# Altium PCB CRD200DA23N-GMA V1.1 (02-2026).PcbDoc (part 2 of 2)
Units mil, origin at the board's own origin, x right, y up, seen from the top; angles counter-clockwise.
Board outline 11500 x 10500 mil, 6 copper layers (Top Layer, Layer 1, Layer 2, Layer 3, Layer 4, Bottom Layer), stack 92.199 mil thick; 97 components, 36 nets, 406 pads, 60 vias.
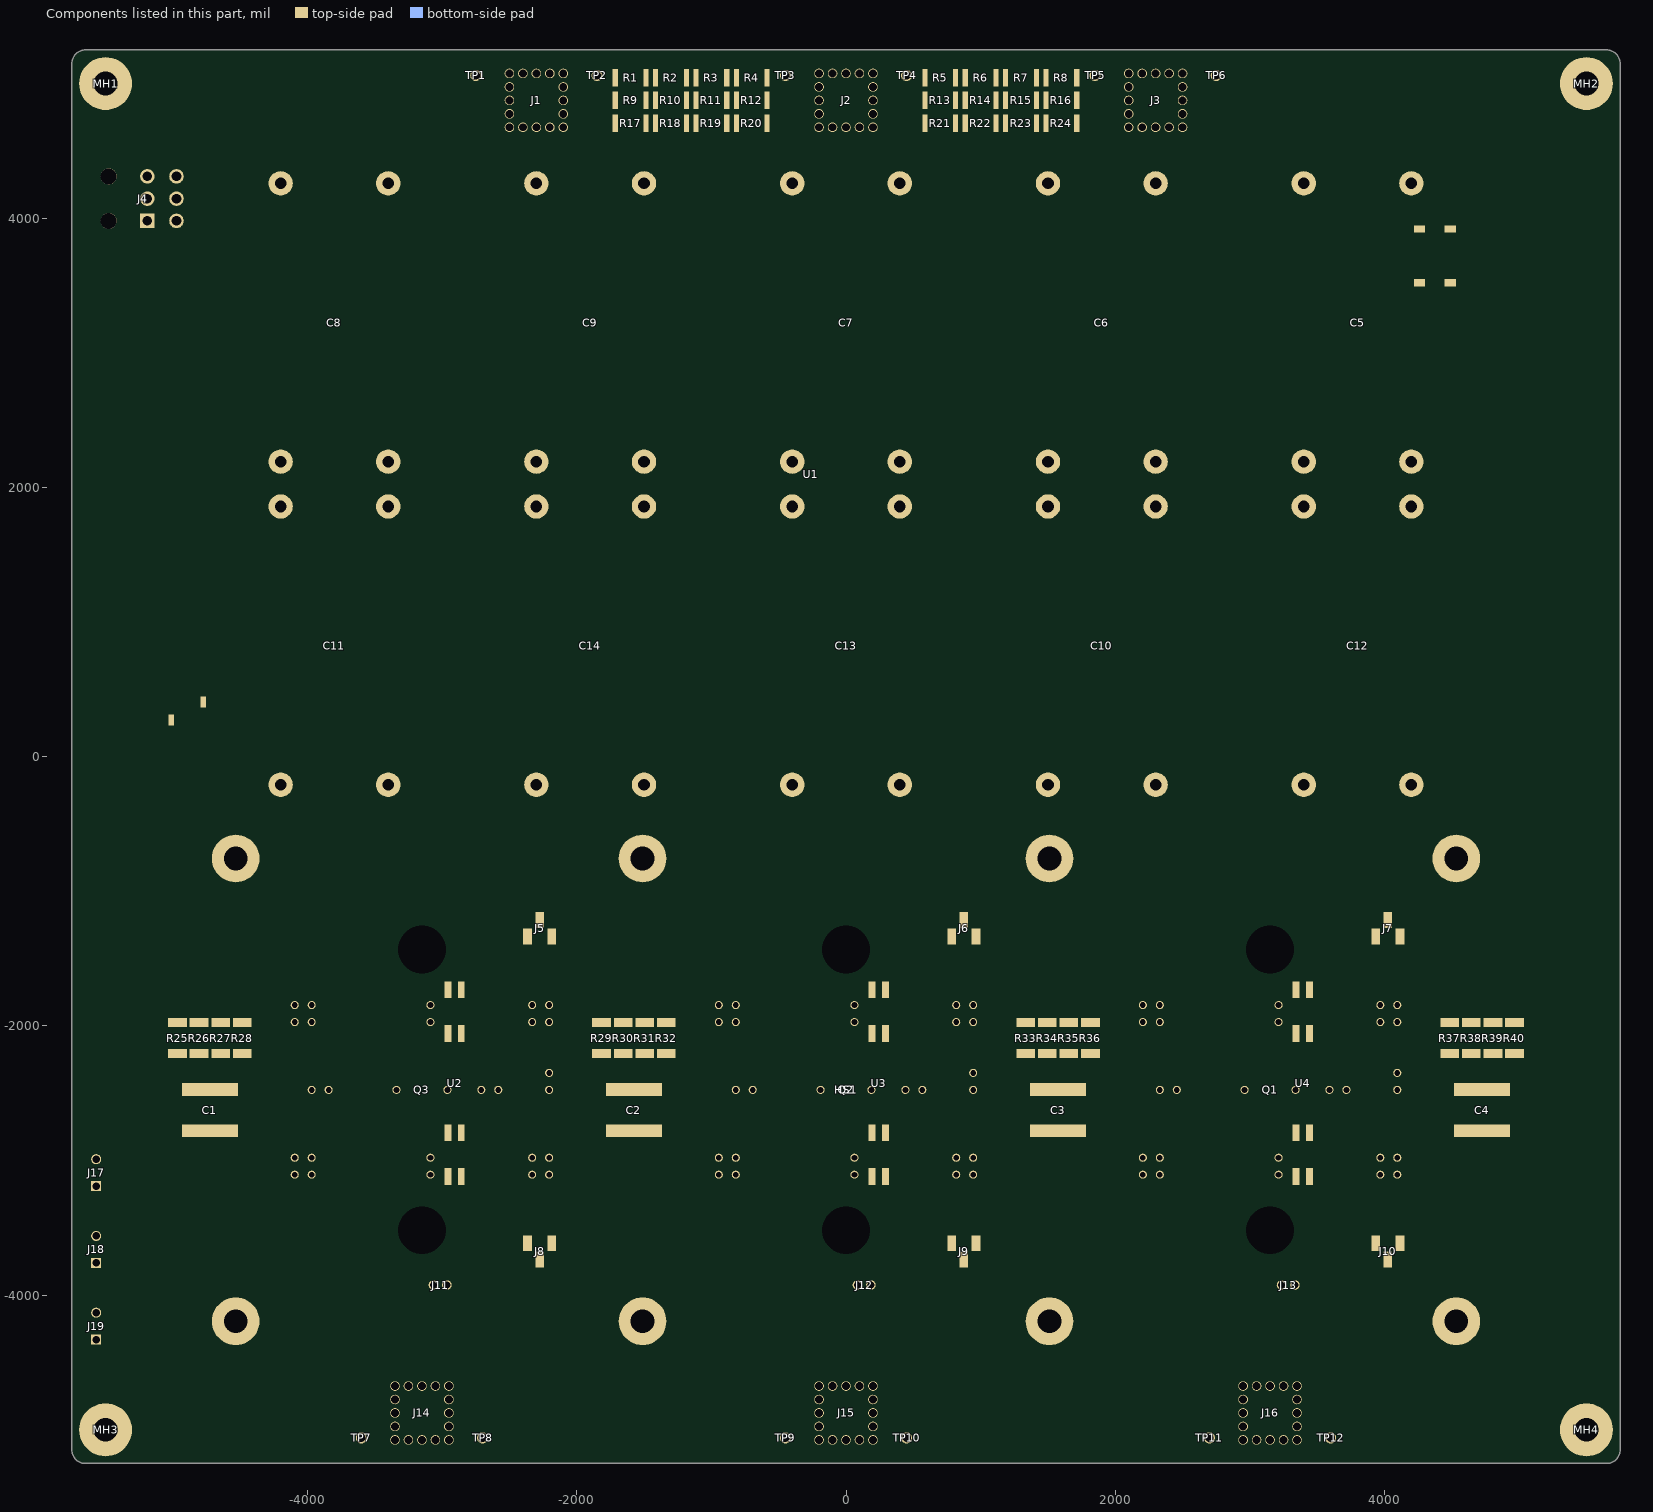
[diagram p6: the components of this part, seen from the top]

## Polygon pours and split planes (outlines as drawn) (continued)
+12V on Layer 2 "Layer 2-+12V" (solid, pour order 417): -5549.4,-4484.91 ccw(c-5555.06,-4380) -5450,-4380 -5450,95 cw(c-5344.94,95) -5348.49,200 -4841.51,200 ccw(c-4845.06,305) -4740,305 -4740,378.49 ccw(c-4845,374.94) -4845,480 -5345,480 cw(c-5345,585.06) -5450,581.51 -5450,3544.99 -5450,3545 cw(c-5345,3545) -5345,3650 -4905,3650 ccw(c-4905,3755) -4800,3755 -4800,4345.16 ccw(c-4904.83,4345.17) -4905,4450 -5545,4450 ccw(c-5545.11,4345.11) -5650,4345 -5650,-4383.5 ccw(c-5545,-4379.94)
U on Layer 1 "Layer 1-U" (solid, pour order 563): -4200.03,-5044.92 ccw(c-4094.97,-5044.91) -4094.97,-5149.97 -2201.54,-5149.97 ccw(c-2205.09,-5044.97) -2100.03,-5044.97 -2100.03,-3055 ccw(c-2203.28,-3053.25) -2205.03,-2950 -2410,-2950 ccw(c-2408.2,-3056.8) -2515,-3055 -2515,-3530 cw(c-2839.99,-3530.01) -2599.19,-3748.26 -2705,-3935 -2705,-3936.87 cw(c-2970.85,-3919.15) -2988.57,-4185 -3075,-4185 cw(c-3075,-3935) -3325,-3935 -3396.16,-3750.32 cw(c-3155,-3525) -3485,-3530 -3485,-3055 ccw(c-3591.8,-3056.8) -3590,-2950 -4094.97,-2950 ccw(c-4093.71,-3056.26) -4199.97,-3055 -4199.97,-5041.36 ccw(c-4094.88,-5044.92)
W on Layer 1 "Layer 1-W" (solid, pour order 562): 2099.97,-5044.92 ccw(c2205.03,-5044.91) 2205.03,-5149.97 4098.46,-5149.97 ccw(c4094.91,-5044.97) 4199.97,-5044.97 4199.97,-3055 ccw(c4096.72,-3053.25) 4094.97,-2950 3890,-2950 ccw(c3891.8,-3056.8) 3785,-3055 3785,-3530 cw(c3460.01,-3530.01) 3700.81,-3748.26 3595,-3935 3595,-3936.87 cw(c3329.15,-3919.15) 3311.43,-4185 3225,-4185 cw(c3225,-3935) 2975,-3935 2903.84,-3750.32 cw(c3145,-3525) 2815,-3530 2815,-3055 ccw(c2708.2,-3056.8) 2710,-2950 2205.03,-2950 ccw(c2206.29,-3056.26) 2100.03,-3055 2100.03,-5041.36 ccw(c2205.12,-5044.92)
V on Layer 1 "Layer 1-V" (solid, pour order 561): -1050.03,-5044.92 ccw(c-944.97,-5044.91) -944.97,-5149.97 948.46,-5149.97 ccw(c944.91,-5044.97) 1049.97,-5044.97 1049.97,-3055 ccw(c946.72,-3053.25) 944.97,-2950 740,-2950 ccw(c741.8,-3056.8) 635,-3055 635,-3530 cw(c310.01,-3530.01) 550.81,-3748.26 445,-3935 445,-3936.87 cw(c179.15,-3919.15) 161.43,-4185 75,-4185 cw(c75,-3935) -175,-3935 -246.16,-3750.32 cw(c-5,-3525) -335,-3530 -335,-3055 ccw(c-441.8,-3056.8) -440,-2950 -944.97,-2950 ccw(c-943.71,-3056.26) -1049.97,-3055 -1049.97,-5041.36 ccw(c-944.88,-5044.92)
DC- on Layer 1 "Layer 1-DC-" (solid, pour order 535): -4930,-2915 -4095,-2915 -4095,-2730 -2215,-2730 -2215,-2915 -945,-2915 -945,-2730 935,-2730 935,-2915 2205,-2915 2205,-2730 4085,-2730 4085,-2915 5445,-2915 ccw(c5445,-2810) 5550,-2810 5550,4348.5 ccw(c5445,4344.94) 5445,4450 3100,4450 cw(c3100,4555.06) 2995,4551.51 2995,5048.49 ccw(c2890,5044.94) 2890,5150 751.51,5150 ccw(c755.05,5045) 650,5045 650,3955 cw(c544.95,3954.99) 548.49,3850 -2565,3850 -2600,3850 cw(c-2600,3955.06) -2705,3951.51 -2705,4348.49 ccw(c-2810,4344.94) -2810,4450 -4268.49,4450 ccw(c-4264.95,4345.01) -4370,4345 -4370,3325 cw(c-4475.05,3324.99) -4471.51,3220 -4933.49,3220 ccw(c-4929.95,3115.01) -5035,3115 -5035,996.51 ccw(c-4930,1000.06) -4930,895 -4805,895 cw(c-4859.94,462.65) -4424.14,457.59 -4424.14,222.41 cw(c-4859.94,217.35) -4805,-215 -4933.49,-215 ccw(c-4929.94,-320) -5035,-320 -5035,-2273.49 ccw(c-4930,-2269.94) -4939.18,-2374.6 -4360,-2374.6 -4360,-2735.4 -4956.91,-2735.4 ccw(c-4956.92,-2813.49) -5035,-2813.49 ccw(c-4930,-2809.94)
S_ULS on Layer 1 "NONET_L02_P-001" (solid, pour order 332): -2850,-3183 ccw(c-2850,-3138) -2805,-3138 -2805,-2768 ccw(c-2850,-2768) -2850,-2723 -3075,-2723 ccw(c-3075,-2768) -3120,-2768 -3120,-3138 ccw(c-3075,-3138) -3075,-3183
S_UHS on Layer 1 "NONET_L02_P-001" (solid, pour order 53): -2850,-2120 ccw(c-2850,-2075) -2805,-2075 -2805,-1705 ccw(c-2850,-1705) -2850,-1660 -3075,-1660 ccw(c-3075,-1705) -3120,-1705 -3120,-2075 ccw(c-3075,-2075) -3075,-2120
S_WLS on Layer 1 "NONET_L02_P-001" (solid, pour order 339): 3450,-3183 ccw(c3450,-3138) 3495,-3138 3495,-2768 ccw(c3450,-2768) 3450,-2723 3225,-2723 ccw(c3225,-2768) 3180,-2768 3180,-3138 ccw(c3225,-3138) 3225,-3183
S_WHS on Layer 1 "NONET_L02_P-001" (solid, pour order 16): 3450,-2120 ccw(c3450,-2075) 3495,-2075 3495,-1705 ccw(c3450,-1705) 3450,-1660 3225,-1660 ccw(c3225,-1705) 3180,-1705 3180,-2075 ccw(c3225,-2075) 3225,-2120
S_VLS on Layer 1 "NONET_L02_P-001" (solid, pour order 335): 300,-3183 ccw(c300,-3138) 345,-3138 345,-2768 ccw(c300,-2768) 300,-2723 75,-2723 ccw(c75,-2768) 30,-2768 30,-3138 ccw(c75,-3138) 75,-3183
S_VHS on Layer 1 "NONET_L02_P-001" (solid, pour order 18): 300,-2120 ccw(c300,-2075) 345,-2075 345,-1705 ccw(c300,-1705) 300,-1660 75,-1660 ccw(c75,-1705) 30,-1705 30,-2075 ccw(c75,-2075) 75,-2120
DC+ on Layer 1 "Layer 1-DC+" (solid, pour order 514): -1351.51,4120 ccw(c-1355.06,4225) -1250,4224.79 -1250,4270 ccw(c-1355,4270) -1355,4375 -1590,4375 cw(c-1590,4480) -1695,4480 -1695,5048.49 ccw(c-1800,5044.94) -1799.85,5150 -2895,5150 ccw(c-2895,5050) -2995,5050 -2995,4771.51 ccw(c-2890,4775.06) -2890,4670 -2540,4670 cw(c-2540,4564.94) -2435,4568.49 -2435,4221.51 ccw(c-2330,4225.06) -2330,4120
MID on Layer 1 "Layer 1-MID" (solid, pour order 513): -490,4246.51 ccw(c-385,4250.06) -385,4145 388.49,4145 ccw(c384.94,4250) 490,4250 490,5048.49 ccw(c385,5044.94) 385,5150 -388.49,5150 ccw(c-384.94,5045) -490,5045
GND on Layer 1 "Layer 1-GND" (solid, pour order 10): -5549.4,-4484.91 ccw(c-5555.06,-4380) -5450,-4380 -5450,95 cw(c-5344.94,95) -5348.49,200 -4841.51,200 ccw(c-4845.06,305) -4740,305 -4740,378.49 ccw(c-4845,374.94) -4845,480 -5345,480 cw(c-5345,585.06) -5450,581.51 -5450,3544.99 -5450,3545 cw(c-5345,3545) -5345,3650 -4905,3650 ccw(c-4905,3755) -4800,3755 -4800,4345.16 ccw(c-4904.83,4345.17) -4905,4450 -5545,4450 ccw(c-5545.11,4345.11) -5650,4345 -5650,-4383.5 ccw(c-5545,-4379.94)
U on Layer 3 "Layer 1-U" (solid, pour order 557): -4200.03,-5044.92 ccw(c-4094.97,-5044.91) -4094.97,-5149.97 -2201.54,-5149.97 ccw(c-2205.09,-5044.97) -2100.03,-5044.97 -2100.03,-3055 ccw(c-2203.28,-3053.25) -2205.03,-2950 -2410,-2950 ccw(c-2408.2,-3056.8) -2515,-3055 -2515,-3530 cw(c-2839.99,-3530.01) -2599.19,-3748.26 -2705,-3935 -2705,-3936.87 cw(c-2970.85,-3919.15) -2988.57,-4185 -3075,-4185 cw(c-3075,-3935) -3325,-3935 -3396.16,-3750.32 cw(c-3155,-3525) -3485,-3530 -3485,-3055 ccw(c-3591.8,-3056.8) -3590,-2950 -4094.97,-2950 ccw(c-4093.71,-3056.26) -4199.97,-3055 -4199.97,-5041.36 ccw(c-4094.88,-5044.92)
W on Layer 3 "Layer 1-W" (solid, pour order 559): 2099.97,-5044.92 ccw(c2205.03,-5044.91) 2205.03,-5149.97 4098.46,-5149.97 ccw(c4094.91,-5044.97) 4199.97,-5044.97 4199.97,-3055 ccw(c4096.72,-3053.25) 4094.97,-2950 3890,-2950 ccw(c3891.8,-3056.8) 3785,-3055 3785,-3530 cw(c3460.01,-3530.01) 3700.81,-3748.26 3595,-3935 3595,-3936.87 cw(c3329.15,-3919.15) 3311.43,-4185 3225,-4185 cw(c3225,-3935) 2975,-3935 2903.84,-3750.32 cw(c3145,-3525) 2815,-3530 2815,-3055 ccw(c2708.2,-3056.8) 2710,-2950 2205.03,-2950 ccw(c2206.29,-3056.26) 2100.03,-3055 2100.03,-5041.36 ccw(c2205.12,-5044.92)
V on Layer 3 "Layer 1-V" (solid, pour order 558): -1050.03,-5044.92 ccw(c-944.97,-5044.91) -944.97,-5149.97 948.46,-5149.97 ccw(c944.91,-5044.97) 1049.97,-5044.97 1049.97,-3055 ccw(c946.72,-3053.25) 944.97,-2950 740,-2950 ccw(c741.8,-3056.8) 635,-3055 635,-3530 cw(c310.01,-3530.01) 550.81,-3748.26 445,-3935 445,-3936.87 cw(c179.15,-3919.15) 161.43,-4185 75,-4185 cw(c75,-3935) -175,-3935 -246.16,-3750.32 cw(c-5,-3525) -335,-3530 -335,-3055 ccw(c-441.8,-3056.8) -440,-2950 -944.97,-2950 ccw(c-943.71,-3056.26) -1049.97,-3055 -1049.97,-5041.36 ccw(c-944.88,-5044.92)
DC- on Layer 3 "Layer 3-DC-" (solid, pour order 533): 2205,-2730 4085,-2730 4085,-2915 5445,-2915 ccw(c5445,-2810) 5550,-2810 5550,4348.5 ccw(c5445,4344.94) 5445,4450 3100,4450 cw(c3100,4555.06) 2995,4551.51 2995,5048.49 ccw(c2890,5044.94) 2890,5150 751.51,5150 ccw(c755.06,5045) 650,5045 650,3955 cw(c544.94,3955) 548.49,3850 -2565,3850 -2600,3850 cw(c-2600,3955.06) -2705,3951.51 -2705,4348.49 ccw(c-2810,4344.94) -2810,4450 -4268.49,4450 ccw(c-4264.94,4345) -4370,4345 -4370,3325 cw(c-4475.06,3325) -4471.51,3220 -4933.49,3220 ccw(c-4929.94,3115) -5035,3115 -5035,995 ccw(c-4935,995) -4935,895 -4855,895 cw(c-4855,465) -4425,465 -4425,215 cw(c-4855,215) -4855,-215 -4935,-215 ccw(c-4935,-315) -5035,-315 -5035,-375 -5035,-2273.49 ccw(c-4930,-2269.94) -4939.18,-2374.6 -4360,-2374.6 -4360,-2735.4 -4956.91,-2735.4 ccw(c-4956.91,-2813.49) -5035,-2813.49 ccw(c-4930,-2809.94) -4930,-2915 -4095,-2915 -4095,-2730 -2215,-2730 -2215,-2915 -945,-2915 -945,-2730 935,-2730 935,-2915 2205,-2915
DC+ on Layer 3 "Layer 3-DC+" (solid, pour order 512): -1351.51,4120 ccw(c-1355.06,4225) -1250,4224.79 -1250,4270 ccw(c-1355,4270) -1355,4375 -1590,4375 cw(c-1590,4480) -1695,4480 -1695,5048.49 ccw(c-1800,5044.94) -1799.85,5150 -2895,5150 ccw(c-2895,5050) -2995,5050 -2995,4771.51 ccw(c-2890,4775.06) -2890,4670 -2540,4670 cw(c-2540,4564.94) -2435,4568.49 -2435,4221.51 ccw(c-2330,4225.06) -2330,4120
MID on Layer 3 "Layer 3-MID" (solid, pour order 499): -490,4246.51 ccw(c-385,4250.06) -385,4145 388.49,4145 ccw(c384.94,4250) 490,4250 490,5048.49 ccw(c385,5044.94) 385,5150 -388.49,5150 ccw(c-384.94,5045) -490,5045
GND on Layer 3 "Layer 3-GND" (solid, pour order 418): -5549.4,-4484.91 ccw(c-5555.06,-4380) -5450,-4380 -5450,95 cw(c-5344.94,95) -5348.49,200 -4841.51,200 ccw(c-4845.06,305) -4740,305 -4740,378.49 ccw(c-4845,374.94) -4845,480 -5345,480 cw(c-5345,585.06) -5450,581.51 -5450,3544.99 -5450,3545 cw(c-5345,3545) -5345,3650 -4905,3650 ccw(c-4905,3755) -4800,3755 -4800,4345.16 ccw(c-4904.83,4345.17) -4905,4450 -5545,4450 ccw(c-5545.11,4345.11) -5650,4345 -5650,-4383.5 ccw(c-5545,-4379.94)
DC- on Bottom Layer "Bottom Layer-DC-" (solid, pour order 473): -5035,-2418.49 ccw(c-4930,-2414.94) -4938.43,-2519.66 -4485,-2520 -4485,-2595 5448.49,-2595 ccw(c5444.94,-2490) 5550,-2490.02 5550,4348.49 ccw(c5445,4344.94) 5445,4450 3100,4450 cw(c3100,4555.06) 2995,4551.51 2995,5053.49 ccw(c2890,5049.94) 2890,5155 751.51,5155 ccw(c755.06,5050) 650,5050 650,3955 cw(c544.94,3955) 548.49,3850 -2855,3850 -2890,3850 cw(c-2890,3955.06) -2994.94,3950.04 -2994.94,4344.94 ccw(c-3100,4344.94) -3099.83,4450 -4268.51,4450 ccw(c-4264.94,4345) -4370,4345 -4370,3325 cw(c-4475.06,3325) -4471.51,3220 -4933.49,3220 ccw(c-4929.94,3115) -5035,3115 -5035,995 ccw(c-4935,995) -4935,895 -4855,895 cw(c-4855,465) -4425,465 -4425,299.02 ccw(c-4320,302.56) -4323.97,197.58 -3397.57,197.57 cw(c-3397.57,-205.64) -2994.36,-205.65 cw(c-3403.2,-205.66) -3403.21,-614.5 -3880,-614.5 -3880,-614.94 -3884.94,-614.94 ccw(c-3884.94,-750) -4020,-750 -4020,-755 cw(c-4530,-755) -4530,-1265 -4933.49,-1265 ccw(c-4929.94,-1370) -5035,-1370
W on Bottom Layer "Bottom Layer-W" (solid, pour order 555): 2205.02,-5149.97 4098.46,-5149.97 ccw(c4094.91,-5044.98) 4199.97,-5044.97 4199.97,-3013.61 ccw(c4094.98,-3010.06) 4094.97,-2905 3886.5,-2905 ccw(c3890.06,-3010) 3785,-3010 3785,-3670 3685,-3770 3685,-3940.84 cw(c3374.72,-3964.71) 3398.57,-4275 3223.49,-4275 cw(c3223.49,-3936.51) 2885,-3936.51 2885,-3770 2815,-3700 2815,-3006.51 ccw(c2710.01,-3010.05) 2710,-2905 2202.58,-2905 ccw(c2205.08,-3010.02) 2100.03,-3010.03 2100.03,-5041.36 ccw(c2204.79,-5044.91) 2099.97,-5044.91 ccw(c2205.02,-5044.92)
V on Bottom Layer "Bottom Layer-V" (solid, pour order 554): -944.98,-5149.97 948.46,-5149.97 ccw(c944.91,-5044.98) 1049.97,-5044.97 1049.97,-3013.61 ccw(c944.98,-3010.06) 944.97,-2905 736.5,-2905 ccw(c740.06,-3010) 635,-3010 635,-3670 535,-3770 535,-3940.84 cw(c224.72,-3964.71) 248.57,-4275 73.49,-4275 cw(c73.49,-3936.51) -265,-3936.51 -265,-3770 -335,-3700 -335,-3006.51 ccw(c-439.99,-3010.05) -440,-2905 -947.42,-2905 ccw(c-944.92,-3010.02) -1049.97,-3010.03 -1049.97,-5041.36 ccw(c-945.21,-5044.91) -1050.03,-5044.91 ccw(c-944.98,-5044.92)
U on Bottom Layer "Bottom Layer-U" (solid, pour order 550): -4094.98,-5149.97 -2201.54,-5149.97 ccw(c-2205.09,-5044.98) -2100.03,-5044.97 -2100.03,-3013.61 ccw(c-2205.02,-3010.06) -2205.03,-2905 -2413.5,-2905 ccw(c-2409.94,-3010) -2515,-3010 -2515,-3670 -2615,-3770 -2615,-3940.84 cw(c-2925.28,-3964.71) -2901.43,-4275 -3076.51,-4275 cw(c-3076.51,-3936.51) -3415,-3936.51 -3415,-3770 -3485,-3700 -3485,-3006.51 ccw(c-3589.99,-3010.05) -3590,-2905 -4097.42,-2905 ccw(c-4094.92,-3010.02) -4199.97,-3010.03 -4199.97,-5041.36 ccw(c-4095.21,-5044.91) -4200.03,-5044.91 ccw(c-4094.98,-5044.92)
DC+ on Bottom Layer "Bottom Layer-DC+" (solid, pour order 527): -2790,4771.51 ccw(c-2685,4775.06) -2685,4670 -2540,4670 cw(c-2540,4564.94) -2435,4568.49 -2435,4266.51 ccw(c-2330,4270.06) -2330,4165 -1351.51,4165 ccw(c-1355.06,4270) -1250,4269.68 -1250,4270 ccw(c-1355,4270) -1355,4375 -1590,4375 cw(c-1590,4480) -1695,4480 -1695,5048.49 ccw(c-1800,5044.94) -1799.85,5150 -2693.5,5150 ccw(c-2689.94,5045) -2790,5077.02
MID on Bottom Layer "Bottom Layer-MID" (solid, pour order 518): -490,4246.51 ccw(c-385,4250.06) -385,4145 388.49,4145 ccw(c384.94,4250) 490,4250 490,5048.49 ccw(c385,5044.94) 385,5150 -388.49,5150 ccw(c-384.94,5045) -490,5045
GND on Bottom Layer "Bottom Layer-GND" (solid, pour order 420): -5549.4,-4484.91 ccw(c-5555.06,-4380) -5450,-4380 -5450,95 cw(c-5344.94,95) -5348.49,200 -4841.51,200 ccw(c-4845.06,305) -4740,305 -4740,378.49 ccw(c-4845,374.94) -4845,480 -5345,480 cw(c-5345,585.06) -5450,581.51 -5450,3544.99 -5450,3545 cw(c-5345,3545) -5345,3650 -4905,3650 ccw(c-4905,3755) -4800,3755 -4800,4345.16 ccw(c-4904.83,4345.17) -4905,4450 -5545,4450 ccw(c-5545.11,4345.11) -5650,4345 -5650,-4383.5 ccw(c-5545,-4379.94)
U on Layer 4 "Layer 4-U" (solid, pour order 564): -2100.03,-3054.88 ccw(c-2203.28,-3053.25) -2100.03,-3051.62 -2100.03,-3013.61 ccw(c-2205.03,-3010.06) -2205.03,-2905 -2413.5,-2905 ccw(c-2409.94,-3010) -2515,-3010 -2515,-3055 ccw(c-2408.2,-3056.8) -2515,-3055 -2515,-3530 cw(c-2839.99,-3530.01) -2599.19,-3748.26 -2705,-3935 -2705,-3936.87 cw(c-2970.85,-3919.15) -2988.57,-4185 -3075,-4185 cw(c-3075,-3935) -3325,-3935 -3396.16,-3750.32 cw(c-3155,-3525) -3485,-3530 -3485,-3006.51 ccw(c-3590,-3010.06) -3590,-2905 -4097.42,-2905 ccw(c-4094.92,-3010.02) -4199.97,-3010.03 -4199.97,-5041.36 ccw(c-4094.88,-5044.92) -4200.03,-5044.92 ccw(c-4094.97,-5044.91) -4094.97,-5149.97 ccw(c-4094.97,-5044.91) -4094.97,-5149.97 -2201.54,-5149.97 ccw(c-2205.09,-5044.97) -2100.03,-5044.97
W on Layer 4 "Layer 4-W" (solid, pour order 566): 4199.97,-3054.88 ccw(c4096.72,-3053.25) 4199.97,-3051.62 4199.97,-3013.61 ccw(c4094.97,-3010.06) 4094.97,-2905 3886.5,-2905 ccw(c3890.06,-3010) 3785,-3010 3785,-3055 ccw(c3891.8,-3056.8) 3785,-3055 3785,-3530 cw(c3460.01,-3530.01) 3700.81,-3748.26 3595,-3935 3595,-3936.87 cw(c3329.15,-3919.15) 3311.43,-4185 3225,-4185 cw(c3225,-3935) 2975,-3935 2903.84,-3750.32 cw(c3145,-3525) 2815,-3530 2815,-3006.51 ccw(c2710,-3010.06) 2710,-2905 2202.58,-2905 ccw(c2205.08,-3010.02) 2100.03,-3010.03 2100.03,-5041.36 ccw(c2205.12,-5044.92) 2099.97,-5044.92 ccw(c2205.03,-5044.91) 2205.03,-5149.97 ccw(c2205.03,-5044.91) 2205.03,-5149.97 4098.46,-5149.97 ccw(c4094.91,-5044.97) 4199.97,-5044.97
V on Layer 4 "Layer 4-V" (solid, pour order 565): 1049.97,-3054.88 ccw(c946.72,-3053.25) 1049.97,-3051.62 1049.97,-3013.61 ccw(c944.97,-3010.06) 944.97,-2905 736.5,-2905 ccw(c740.06,-3010) 635,-3010 635,-3055 ccw(c741.8,-3056.8) 635,-3055 635,-3530 cw(c310.01,-3530.01) 550.81,-3748.26 445,-3935 445,-3936.87 cw(c179.15,-3919.15) 161.43,-4185 75,-4185 cw(c75,-3935) -175,-3935 -246.16,-3750.32 cw(c-5,-3525) -335,-3530 -335,-3006.51 ccw(c-440,-3010.06) -440,-2905 -947.42,-2905 ccw(c-944.92,-3010.02) -1049.97,-3010.03 -1049.97,-5041.36 ccw(c-944.88,-5044.92) -1050.03,-5044.92 ccw(c-944.97,-5044.91) -944.97,-5149.97 ccw(c-944.97,-5044.91) -944.97,-5149.97 948.46,-5149.97 ccw(c944.91,-5044.97) 1049.97,-5044.97
DC+ on Layer 4 "Layer 4-DC+" (solid, pour order 531): 3815,-2005 5448.49,-2005 ccw(c5444.94,-1900) 5550,-1900 5550,3748.49 ccw(c5445,3744.94) 5445.2,3850 -545,3850 cw(c-545,3955.06) -650,3951.51 -650,5048.49 ccw(c-755,5044.94) -755,5150 -2893.49,5150 ccw(c-2889.94,5045) -2995,5045 -2995,3955 cw(c-3100.06,3955) -3096.51,3850 -4268.49,3850 ccw(c-4264.94,3745) -4370,3745 -4370,3325 cw(c-4475.06,3325) -4471.51,3220 -4933.49,3220 ccw(c-4929.94,3115) -5035,3115 -5035,995 ccw(c-4935,995) -4935,895 -4855,895 cw(c-4855,465) -4425,465 -4425,215 cw(c-4855,215) -4855,-215 -4935,-215 ccw(c-4935,-315) -5035,-315 -5035,-1903.49 ccw(c-4930,-1899.94) -4930,-2005 -3446.51,-2005 ccw(c-3450.06,-1900) -3345,-1900 -3345,-1435 -2815,-1435 -2815,-1675 -2485,-2005 -296.51,-2005 ccw(c-300.06,-1900) -195,-1900 -195,-1435 335,-1435 335,-1675 665,-2005 2853.49,-2005 ccw(c2849.94,-1900) 2955,-1900 2955,-1435 3485,-1435 3485,-1675
MID on Layer 4 "Layer 4-MID" (solid, pour order 515): -490,4180 ccw(c-378.11,4181.89) -380,4070 385,4070 ccw(c383.19,4176.81) 490,4175 490,5048.49 ccw(c385,5044.94) 385,5150 -388.49,5150 ccw(c-384.94,5045) -490,5045
DC- on Layer 4 "Layer 4-DC-" (solid, pour order 488): 1345,4070 5448.49,4070 ccw(c5444.94,4175) 5550,4175 5550,4341.39 ccw(c5445,4344.94) 5445,4450 3100,4450 cw(c3100,4555.06) 2995,4551.51 2995,5048.49 ccw(c2890,5044.94) 2890,5150 1796.51,5150 ccw(c1800.06,5045) 1695,5045 1695,4480 cw(c1589.95,4479.99) 1593.49,4375 1341.51,4375 ccw(c1345.06,4270) 1240,4270 1240,4171.51 ccw(c1345,4175.06)
+12V on Layer 4 "Layer 4-+12V" (solid, pour order 419): -5549.4,-4484.91 ccw(c-5555.06,-4380) -5450,-4380 -5450,95 cw(c-5344.94,95) -5348.49,200 -4841.51,200 ccw(c-4845.06,305) -4740,305 -4740,378.49 ccw(c-4845,374.94) -4845,480 -5345,480 cw(c-5345,585.06) -5450,581.51 -5450,3544.99 -5450,3545 cw(c-5345,3545) -5345,3650 -4905,3650 ccw(c-4905,3755) -4800,3755 -4800,4345.16 ccw(c-4904.83,4345.17) -4905,4450 -5545,4450 ccw(c-5545.11,4345.11) -5650,4345 -5650,-4383.5 ccw(c-5545,-4379.94)

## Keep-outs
Layer 1:
  region: -5090,-2605 -5090,-2505 -4360,-2505 -4360,-2605
  region: -1940,-2605 -1940,-2505 -1210,-2505 -1210,-2605
  region: 1210,-2605 1210,-2505 1940,-2505 1940,-2605
  region: 4360,-2605 4360,-2505 5090,-2505 5090,-2605
Layer 3:
  region: -1940,-2605 -1940,-2505 -1210,-2505 -1210,-2605
  region: 1210,-2605 1210,-2505 1940,-2505 1940,-2605
  region: 4360,-2605 4360,-2505 5090,-2505 5090,-2605
  region: -5090,-2605 -5090,-2505 -4360,-2505 -4360,-2605

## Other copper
Top Layer:
  pour cut-out: 2994.35,-205.65 ccw(c3403.21,-205.65) 3403.21,-614.5 4196.79,-614.5 ccw(c4196.79,-205.65) 4605.65,-205.65 ccw(c4202.43,-205.64) 4202.43,197.58 3397.58,197.58 ccw(c3397.58,-205.65)
  pour cut-out: -2705.65,-205.65 ccw(c-2296.79,-205.65) -2296.79,-614.5 -1503.21,-614.5 ccw(c-1503.21,-205.65) -1094.35,-205.65 ccw(c-1497.57,-205.64) -1497.57,197.58 -2302.42,197.58 ccw(c-2302.42,-205.65)
  pour cut-out: -1996.17,-842.04 -1035.18,-628.99 -1094.35,-195.74 -2060,-615
  pour cut-out: 4140.99,-1085.82 4925.94,-427.17 4537.69,18.37 3775,-615
Layer 1:
  pour cut-out: 1115.29,-717.52 1901.03,-678.92 1809.48,-173.64 1189.35,-208.46
  pour cut-out: -2840,-1515 -2765,-1515 -2765,-2220 -2205.12,-2221.46 -2205,-1595 -2608.56,-1595 -2840,-1300
  pour cut-out: -311.88,-1560.88 -185,-2000 -40,-1950 -200,-1520
  pour cut-out: 2838.12,-1560.88 2965,-2000 3110,-1950 2950,-1520
  pour cut-out: -3461.88,-1560.88 -3335,-2000 -3190,-1950 -3350,-1520
  pour cut-out: 3460,-1515 3535,-1515 3535,-2220 4095,-2220 4095,-1595 3690.2,-1595 3460,-1300
  pour cut-out: 310,-1515 385,-1515 385,-2220 945,-2220 945,-1595 540.2,-1595 310,-1300
  pour cut-out: -4853.1,-488.29 -4155.31,-932.83 -3919.37,-343.42 -4419.55,11.47
  pour cut-out: -4450.55,1858.46 -3948.66,1858.46 -3948.66,2191.54 -4450.55,2191.54
  pour cut-out: -3651.34,1858.46 -3149.45,1858.46 -3149.45,2191.54 -3651.34,2191.54
  pour cut-out: -2550.55,1858.46 -2048.66,1858.46 -2048.66,2191.54 -2550.55,2191.54
  pour cut-out: -1751.34,1858.46 -1249.45,1858.46 -1249.45,2191.54 -1751.34,2191.54
  pour cut-out: -710.65,1858.46 -88.57,1858.46 -88.57,2191.54 -710.65,2191.54
  pour cut-out: 88.57,1858.46 710.65,1858.46 710.65,2191.54 88.57,2191.54
  pour cut-out: 1249.45,1858.46 1751.34,1858.46 1751.34,2191.54 1249.45,2191.54
  pour cut-out: 2048.66,1858.46 2550.55,1858.46 2550.55,2191.54 2048.66,2191.54
  pour cut-out: 3149.45,1858.46 3651.34,1858.46 3651.34,2191.54 3149.45,2191.54
  pour cut-out: 3948.66,1858.46 4450.55,1858.46 4450.55,2191.54 3948.66,2191.54
Layer 2:
  pour cut-out: -1906.75,-717.52 -1121.02,-678.92 -1189.35,-208.46 -1809.48,-173.64
  pour cut-out: 3919.37,-343.42 4141.38,-899.2 4853.1,-488.29 4462.97,-42.98
  pour cut-out: -4450.55,1858.46 -3948.66,1858.46 -3948.66,2191.54 -4450.55,2191.54
  pour cut-out: -3651.34,1858.46 -3149.45,1858.46 -3149.45,2191.54 -3651.34,2191.54
  pour cut-out: -2550.55,1858.46 -2048.66,1858.46 -2048.66,2191.54 -2550.55,2191.54
  pour cut-out: -1751.34,1858.46 -1249.45,1858.46 -1249.45,2191.54 -1751.34,2191.54
  pour cut-out: 1249.45,1858.46 1751.34,1858.46 1751.34,2191.54 1249.45,2191.54
  pour cut-out: 2048.66,1858.46 2550.55,1858.46 2550.55,2191.54 2048.66,2191.54
  pour cut-out: 3149.45,1858.46 3651.34,1858.46 3651.34,2191.54 3149.45,2191.54
  pour cut-out: 3948.66,1858.46 4450.55,1858.46 4450.55,2191.54 3948.66,2191.54
Layer 3:
  pour cut-out: 1115.29,-717.52 1901.03,-678.92 1809.48,-173.64 1189.35,-208.46
  pour cut-out: -4853.1,-488.29 -4155.31,-932.83 -3919.37,-343.42 -4419.55,11.47
  pour cut-out: -3461.88,-1560.88 -3335.83,-1999.1 -2704.19,-1787.15 -2826.96,-1333.7
  pour cut-out: 2838.12,-1560.88 2964.17,-1999.1 3595.81,-1787.15 3473.04,-1333.7
  pour cut-out: -311.88,-1560.88 -185.83,-1999.1 445.81,-1787.15 323.04,-1333.7
  pour cut-out: -4450.55,1858.46 -3948.66,1858.46 -3948.66,2191.54 -4450.55,2191.54
  pour cut-out: -3651.34,1858.46 -3149.45,1858.46 -3149.45,2191.54 -3651.34,2191.54
  pour cut-out: -2550.55,1858.46 -2048.66,1858.46 -2048.66,2191.54 -2550.55,2191.54
  pour cut-out: -1751.34,1858.46 -1249.45,1858.46 -1249.45,2191.54 -1751.34,2191.54
  pour cut-out: 1249.45,1858.46 1751.34,1858.46 1751.34,2191.54 1249.45,2191.54
  pour cut-out: 2048.66,1858.46 2550.55,1858.46 2550.55,2191.54 2048.66,2191.54
  pour cut-out: 3149.45,1858.46 3651.34,1858.46 3651.34,2191.54 3149.45,2191.54
  pour cut-out: 3948.66,1858.46 4450.55,1858.46 4450.55,2191.54 3948.66,2191.54
  pour cut-out: -710.65,1858.46 -88.57,1858.46 -88.57,2191.54 -710.65,2191.54
  pour cut-out: 88.57,1858.46 710.65,1858.46 710.65,2191.54 88.57,2191.54
Layer 4:
  pour cut-out: -1906.75,-717.52 -1121.02,-678.92 -1189.35,-208.46 -1809.48,-173.64
  pour cut-out: 3149.45,1858.46 3651.34,1858.46 3651.34,2191.54 3149.45,2191.54
  pour cut-out: 3948.66,1858.46 4450.55,1858.46 4450.55,2191.54 3948.66,2191.54
  pour cut-out: 3919.37,-343.42 4141.38,-899.2 4853.1,-488.29 4462.97,-42.98
  pour cut-out: -1751.34,1858.46 -1249.45,1858.46 -1249.45,2191.54 -1751.34,2191.54
  pour cut-out: -2550.55,1858.46 -2048.66,1858.46 -2048.66,2191.54 -2550.55,2191.54
  pour cut-out: 1249.45,1858.46 1751.34,1858.46 1751.34,2191.54 1249.45,2191.54
  pour cut-out: 2048.66,1858.46 2550.55,1858.46 2550.55,2191.54 2048.66,2191.54
  pour cut-out: -3651.34,1858.46 -3149.45,1858.46 -3149.45,2191.54 -3651.34,2191.54
  pour cut-out: -4450.55,1858.46 -3948.66,1858.46 -3948.66,2191.54 -4450.55,2191.54
Bottom Layer:
  pour cut-out: -3425.79,-1989.21 ccw(c-3100.19,-1989.21) -3100.18,-2314.82 -2180,-2314.82 ccw(c-2180,-2000.5) -1865.69,-2000.5 -1865.69,-1834.31 ccw(c-2194.35,-1834.31) -2194.35,-1505.65 -2679.1,-1505.65 cw(c-2679.1,-1365.84) -2818.91,-1365.84 ccw(c-2819.75,-1365.84) -2819.75,-1365 -3425.79,-1365
  pour cut-out: -275.79,-1989.21 ccw(c49.81,-1989.21) 49.82,-2314.82 970,-2314.82 ccw(c970,-2000.5) 1284.31,-2000.5 1284.31,-1834.31 ccw(c955.65,-1834.31) 955.65,-1505.65 470.9,-1505.65 cw(c470.9,-1365.84) 331.09,-1365.84 ccw(c330.25,-1365.84) 330.25,-1365 -275.79,-1365
  pour cut-out: 2874.21,-1989.21 ccw(c3199.81,-1989.21) 3199.82,-2314.82 4120,-2314.82 ccw(c4120,-2000.5) 4434.31,-2000.5 4434.31,-1834.31 ccw(c4105.65,-1834.31) 4105.65,-1505.65 3620.9,-1505.65 cw(c3620.9,-1365.84) 3481.09,-1365.84 ccw(c3480.25,-1365.84) 3480.25,-1365 2874.21,-1365
  pour cut-out: -805.65,1858.46 ccw(c-399.61,1858.46) -399.61,1452.42 402.42,1452.42 ccw(c402.43,1855.64) 805.65,1855.65 805.65,2194.35 ccw(c402.43,2194.35) 402.42,2597.58 -402.42,2597.58 ccw(c-402.43,2194.35) -805.65,2194.35
  pour cut-out: 1094.35,-205.65 ccw(c1503.21,-205.65) 1503.21,-614.5 2296.79,-614.5 ccw(c2296.79,-205.65) 2705.65,-205.65 ccw(c2302.43,-205.64) 2302.43,197.58 1497.58,197.58 ccw(c1497.58,-205.65)
  pour cut-out: 3948.66,1858.46 4450.55,1858.46 4450.55,2191.54 3948.66,2191.54
  pour cut-out: 3149.45,1858.46 3651.34,1858.46 3651.34,2191.54 3149.45,2191.54
  pour cut-out: 2048.66,1858.46 2550.55,1858.46 2550.55,2191.54 2048.66,2191.54
  pour cut-out: 1249.45,1858.46 1751.34,1858.46 1751.34,2191.54 1249.45,2191.54
  pour cut-out: -1751.34,1858.46 -1249.45,1858.46 -1249.45,2191.54 -1751.34,2191.54
  pour cut-out: -2550.55,1858.46 -2048.66,1858.46 -2048.66,2191.54 -2550.55,2191.54
  pour cut-out: -3651.34,1858.46 -3149.45,1858.46 -3149.45,2191.54 -3651.34,2191.54
  pour cut-out: -4450.55,1858.46 -3948.66,1858.46 -3948.66,2191.54 -4450.55,2191.54

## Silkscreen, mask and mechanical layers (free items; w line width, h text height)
Top Overlay:
  drawing of 41 lines, arcs and shapes, not listed
  text "-" at -5152.49,4630.01 h60
  text "+" at -5052.49,4630.01 h60
  text "-" at -5152.49,4565.01 h60
  text "+" at -5052.49,4565.01 h60
  text "-" at -5152.49,4500.01 h60
  text "+" at -5052.49,4500.01 h60
  text "MID" at -249.92,4375.03 h200
  text "+" at -2391.64,4337.54 h275
  text "-" at 2208.36,4337.54 h275
  text "U1A" at 4331.26,4032.51 h35
  text "-" at 4580,3890.01 h60
  text "12V PWR" at -5684.94,3780.01 h60
  text "+" at 4580,3490.01 h60
  text "+" at -4735,390.01 h60
  text "-" at -5051,289.99 h60 r180
  text "U1B" at -4936.74,242.51 h35
  text "2.3KV WOLFPACK GM4 HALF-BRIDGE INVERTER / PN CRD200DA23N-GMA / V1.1, 02/2026" at -2268.75,-879.21 h100
  text "+" at -2294.99,-1419.99 h60
  text "+" at 855.01,-1419.99 h60
  text "+" at 4005.01,-1419.99 h60
  text "U2A" at -2817.49,-1846.85 h35 r270
  text "U3A" at 332.51,-1846.85 h35 r270
  text "U4A" at 3482.51,-1846.85 h35 r270
  text "U2B" at -2817.49,-2909.85 h35 r270
  text "U3B" at 332.51,-2909.85 h35 r270
  text "U4B" at 3482.51,-2909.85 h35 r270
  text "U" at -2294.99,-3589.99 h60
  text "V" at 855.01,-3589.99 h60
  text "W" at 4005.01,-3589.99 h60
  text "U-NTC" at -3154.95,-4139.99 h60
  text "V-NTC" at -4.95,-4139.99 h60
  text "W-NTC" at 3145.05,-4139.99 h60
  text "U" at -3216.65,-4574.97 h200
  text "V" at -66.65,-4574.97 h200
  text "W" at 3083.35,-4574.97 h200
Bottom Overlay:
  text "-" at -5300.01,-3009.99 h60 r90
  text "+" at -5300.01,-3209.99 h60 r90
  text "-" at -5300.01,-3579.99 h60 r90
  text "+" at -5300.01,-3779.99 h60 r90
  text "-" at -5300.01,-4149.99 h60 r90
  text "+" at -5300.01,-4349.99 h60 r90
  text "FANS" at -5440.04,-4564.99 h60
Board Outline:
  lines w1: -5750,-5150 ccw(c-5650,-5150) -5650,-5250 5650,-5250 ccw(c5650,-5150) 5750,-5150 5750,5150 ccw(c5650,5150) 5650,5250 -5650,5250 ccw(c-5650,5150) -5750,5150 -5750,-5150 ; -5030,-2645 cw(c-5030,-2625) -5030,-2605 -4420,-2605 cw(c-4420,-2625) -4420,-2645 -5030,-2645 ; -1880,-2645 cw(c-1880,-2625) -1880,-2605 -1270,-2605 cw(c-1270,-2625) -1270,-2645 -1880,-2645 ; 1270,-2645 cw(c1270,-2625) 1270,-2605 1880,-2605 cw(c1880,-2625) 1880,-2645 1270,-2645 ; 4420,-2645 cw(c4420,-2625) 4420,-2605 5030,-2605 cw(c5030,-2625) 5030,-2645 4420,-2645
Drill Drawing:
  circle w10: c-5649.38,6935.83 r20
  circle w10: c-5649.38,6935.83 r33.33
  circle w10: c-5649.38,6635.83 r33.33
  lines w1: -5750,-5150 ccw(c-5650,-5150) -5650,-5250 5650,-5250 ccw(c5650,-5150) 5750,-5150 5750,5150 ccw(c5650,5150) 5650,5250 -5650,5250 ccw(c-5650,5150) -5750,5150 -5750,-5150 ; -5030,-2645 cw(c-5030,-2625) -5030,-2605 -4420,-2605 cw(c-4420,-2625) -4420,-2645 -5030,-2645 ; -1880,-2645 cw(c-1880,-2625) -1880,-2605 -1270,-2605 cw(c-1270,-2625) -1270,-2645 -1880,-2645 ; 1270,-2645 cw(c1270,-2625) 1270,-2605 1880,-2605 cw(c1880,-2625) 1880,-2645 1270,-2645 ; 4420,-2645 cw(c4420,-2625) 4420,-2605 5030,-2605 cw(c5030,-2625) 5030,-2645 4420,-2645
  lines w10: -5682.71,5569.17 -5666.04,5569.17 -5649.38,5552.5 -5632.71,5569.17 -5616.04,5569.17 -5632.71,5585.83 -5616.04,5602.5 -5632.71,5602.5 -5649.38,5619.17 -5666.04,5602.5 -5682.71,5602.5 -5666.04,5585.83 -5682.71,5569.17 ; -5682.71,5702.5 -5682.71,5719.17 -5666.04,5735.83 -5682.71,5752.5 -5682.71,5769.17 -5666.04,5769.17 -5649.38,5752.5 -5632.71,5769.17 -5616.04,5769.17 -5616.04,5752.5 -5632.71,5735.83 -5616.04,5719.17 -5616.04,5702.5 -5632.71,5702.5 -5649.38,5719.17 -5666.04,5702.5 -5682.71,5702.5 ; -5682.71,5852.5 -5616.04,5852.5 -5616.04,5919.17 -5682.71,5919.17 -5682.71,5852.5 ; -5682.71,6002.5 -5616.04,6002.5 -5616.04,6069.17 -5682.71,6069.17 -5682.71,6002.5 ; -5682.71,6152.5 -5649.38,6169.17 -5616.04,6152.5 -5632.71,6185.83 -5616.04,6219.17 -5649.38,6202.5 -5682.71,6219.17 -5666.04,6185.83 -5682.71,6152.5 ; -5682.71,6369.17 -5616.04,6369.17 -5649.38,6302.5 -5682.71,6369.17 ; -5682.71,6469.17 -5666.04,6469.17 -5666.04,6452.5 -5632.71,6452.5 -5632.71,6469.17 -5616.04,6469.17 -5616.04,6502.5 -5632.71,6502.5 -5632.71,6519.17 -5666.04,6519.17 -5666.04,6502.5 -5682.71,6502.5 -5682.71,6469.17 ; -5682.71,6785.83 -5649.38,6752.5 -5616.04,6785.83 -5649.38,6819.17 -5682.71,6785.83 ; -5682.71,7069.17 -5666.04,7069.17 -5666.04,7052.5 -5632.71,7052.5 -5632.71,7069.17 -5616.04,7069.17 -5616.04,7102.5 -5632.71,7102.5 -5632.71,7119.17 -5666.04,7119.17 -5666.04,7102.5 -5682.71,7102.5 -5682.71,7069.17 ; -5669.38,6015.83 -5629.38,6015.83 -5629.38,6055.83 -5669.38,6055.83 -5669.38,6015.83 ; -5669.38,6355.83 -5629.38,6355.83 -5649.38,6315.83 -5669.38,6355.83 ; -5669.38,7075.83 -5659.38,7075.83 -5659.38,7065.83 -5639.38,7065.83 -5639.38,7075.83 -5629.38,7075.83 -5629.38,7095.83 -5639.38,7095.83 -5639.38,7105.83 -5659.38,7105.83 -5659.38,7095.83 -5669.38,7095.83 -5669.38,7075.83
  lines w15: -5742.5,5507.5 3294.99,5507.5 ; -5742.5,7157.5 3294.99,7157.5 ; -5191.62,5357.5 -5191.62,7307.5 ; -4591.78,5357.5 -4591.78,7307.5 ; -3492.1,5357.5 -3492.1,7307.5 ; -2986.23,5357.5 -2986.23,7307.5 ; -2252.43,5357.5 -2252.43,7307.5 ; -752.87,5357.5 -752.87,7307.5 ; -163.03,5357.5 -163.03,7307.5 ; 582.77,5357.5 582.77,7307.5 ; 1916.38,5357.5 1916.38,7307.5 ; -5742.5,5357.5 3294.99,5357.5 3294.99,7307.5 -5742.5,7307.5 -5742.5,5357.5
  text "*" at -5600,7650 h60
  text "THESE HOLES (1.09 MM +/- 0.065 MM) ARE FOR PRESS-FIT PART. USE 1.18 MM +/- 0.025 MM DRILLED HOLES. COPPER THICKNESS IN HOLE 0.025-0.05 MM. MAXIMUM METALLIZATION THICKNESS IN HOLE 0.015 MM." at -5505,7595 h100
  text "w" at -5730.69,7569.72 h200
  text "^" at -5595,7465.01 h60
  text "THESE HOLES (1.48MM +/- 0.05MM) ARE FOR PRESS-FIT PART. USE 63.0MIL +/- 1MIL DRILLED HOLES. COPPER THICKNESS IN HOLE 25-60UM." at -5500,7400 h100
  text "w" at -5730.69,7381.66 h200
  text "Symbol" at -5652.5,7202.5 h72
  text "Count" at -5146.62,7202.5 h72
  text "Hole Size" at -4546.78,7202.5 h72
  text "Plated" at -3447.1,7202.5 h72
  text "Hole Type" at -2941.23,7202.5 h72
  text "Drill Layer Pair" at -2207.43,7202.5 h72
  text "Via/Pad" at -707.87,7202.5 h72
  text "Pad Shape" at -118.03,7202.5 h72
  text "Hole Tolerance (+)" at 627.77,7202.5 h72
  text "Hole Tolerance (-)" at 1961.38,7202.5 h72
  text "60" at -5146.62,7052.5 h60
  text "0.33mm (13.00mil)" at -4546.78,7052.5 h60
  text "PTH" at -3447.1,7052.5 h60
  text "Round" at -2941.23,7052.5 h60
  text "Top Layer - Bottom Layer" at -2207.43,7052.5 h60
  text "Via" at -707.87,7052.5 h60
  text "Rounded" at -118.03,7052.5 h60
  text "0.10mm (4.00mil)" at 627.77,7052.5 h60
  text "0.10mm (4.00mil)" at 1961.38,7052.5 h60
  text "*" at -5820,6955 h60
  text "84" at -5146.62,6902.5 h60
  text "1.09mm (42.91mil)" at -4546.78,6902.5 h60
  text "PTH" at -3447.1,6902.5 h60
  text "Round" at -2941.23,6902.5 h60
  text "Top Layer - Bottom Layer" at -2207.43,6902.5 h60
  text "Pad" at -707.87,6902.5 h60
  text "Rounded" at -118.03,6902.5 h60
  text "0.07mm (2.56mil)" at 627.77,6902.5 h60
  text "0.07mm (2.56mil)" at 1961.38,6902.5 h60
  text "w" at -5950.69,6874.72 h200
  text "6" at -5146.62,6752.5 h60
  text "1.30mm (51.18mil)" at -4546.78,6752.5 h60
  text "PTH" at -3447.1,6752.5 h60
  text "Round" at -2941.23,6752.5 h60
  text "Top Layer - Bottom Layer" at -2207.43,6752.5 h60
  text "Pad" at -707.87,6752.5 h60
  text "Rounded" at -118.03,6752.5 h60
  text "0.10mm (4.00mil)" at 627.77,6752.5 h60
  text "0.10mm (4.00mil)" at 1961.38,6752.5 h60
  text "6" at -5146.62,6602.5 h60
  text "1.40mm (55.12mil)" at -4546.78,6602.5 h60
  text "PTH" at -3447.1,6602.5 h60
  text "Round" at -2941.23,6602.5 h60
  text "Top Layer - Bottom Layer" at -2207.43,6602.5 h60
  text "Pad" at -707.87,6602.5 h60
  text "(Mixed)" at -118.03,6602.5 h60
  text "0.10mm (4.00mil)" at 627.77,6602.5 h60
  text "0.10mm (4.00mil)" at 1961.38,6602.5 h60
  text "^" at -5820,6510.01 h60
  text "96" at -5146.62,6452.5 h60
  text "1.48mm (58.07mil)" at -4546.78,6452.5 h60
  text "PTH" at -3447.1,6452.5 h60
  text "Round" at -2941.23,6452.5 h60
  text "Top Layer - Bottom Layer" at -2207.43,6452.5 h60
  text "Pad" at -707.87,6452.5 h60
  text "Rounded" at -118.03,6452.5 h60
  text "0.05mm (1.97mil)" at 627.77,6452.5 h60
  text "0.05mm (1.97mil)" at 1961.38,6452.5 h60
  text "w" at -5950.69,6426.66 h200
  text "12" at -5146.62,6302.5 h60
  text "1.60mm (62.99mil)" at -4546.78,6302.5 h60
  text "PTH" at -3447.1,6302.5 h60
  text "Round" at -2941.23,6302.5 h60
  text "Top Layer - Bottom Layer" at -2207.43,6302.5 h60
  text "Pad" at -707.87,6302.5 h60
  text "Rounded" at -118.03,6302.5 h60
  text "0.10mm (4.00mil)" at 627.77,6302.5 h60
  text "0.10mm (4.00mil)" at 1961.38,6302.5 h60
  text "6" at -5146.62,6152.5 h60
  text "1.80mm (70.87mil)" at -4546.78,6152.5 h60
  text "PTH" at -3447.1,6152.5 h60
  text "Round" at -2941.23,6152.5 h60
  text "Top Layer - Bottom Layer" at -2207.43,6152.5 h60
  text "Pad" at -707.87,6152.5 h60
  text "(Mixed)" at -118.03,6152.5 h60
  text "0.10mm (4.00mil)" at 627.77,6152.5 h60
  text "0.10mm (4.00mil)" at 1961.38,6152.5 h60
  text "40" at -5146.62,6002.5 h60
  text "2.20mm (86.61mil)" at -4546.78,6002.5 h60
  text "PTH" at -3447.1,6002.5 h60
  text "Round" at -2941.23,6002.5 h60
  text "Top Layer - Bottom Layer" at -2207.43,6002.5 h60
  text "Pad" at -707.87,6002.5 h60
  text "Rounded" at -118.03,6002.5 h60
  text "0.10mm (4.00mil)" at 627.77,6002.5 h60
  text "0.10mm (4.00mil)" at 1961.38,6002.5 h60
  text "2" at -5146.62,5852.5 h60
  text "3.00mm (118.11mil)" at -4546.78,5852.5 h60
  text "NPTH" at -3447.1,5852.5 h60
  text "Round" at -2941.23,5852.5 h60
  text "Top Layer - Bottom Layer" at -2207.43,5852.5 h60
  text "Pad" at -707.87,5852.5 h60
  text "Rounded" at -118.03,5852.5 h60
  text "0.13mm (5.00mil)" at 627.77,5852.5 h60
  text "0.13mm (5.00mil)" at 1961.38,5852.5 h60
  text "12" at -5146.62,5702.5 h60
  text "4.50mm (177.17mil)" at -4546.78,5702.5 h60
  text "PTH" at -3447.1,5702.5 h60
  text "Round" at -2941.23,5702.5 h60
  text "Top Layer - Bottom Layer" at -2207.43,5702.5 h60
  text "Pad" at -707.87,5702.5 h60
  text "Rounded" at -118.03,5702.5 h60
  text "0.13mm (5.00mil)" at 627.77,5702.5 h60
  text "0.13mm (5.00mil)" at 1961.38,5702.5 h60
  text "6" at -5146.62,5552.5 h60
  text "9.00mm (354.33mil)" at -4546.78,5552.5 h60
  text "NPTH" at -3447.1,5552.5 h60
  text "Round" at -2941.23,5552.5 h60
  text "Top Layer - Bottom Layer" at -2207.43,5552.5 h60
  text "Pad" at -707.87,5552.5 h60
  text "Rounded" at -118.03,5552.5 h60
  text "0.13mm (5.00mil)" at 627.77,5552.5 h60
  text "0.13mm (5.00mil)" at 1961.38,5552.5 h60
  text "330 Total" at -5146.62,5402.5 h60

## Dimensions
-5750,-5150 to 5750,-5150 on Drill Drawing
-5650,-5250 to -5650,5250 on Drill Drawing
